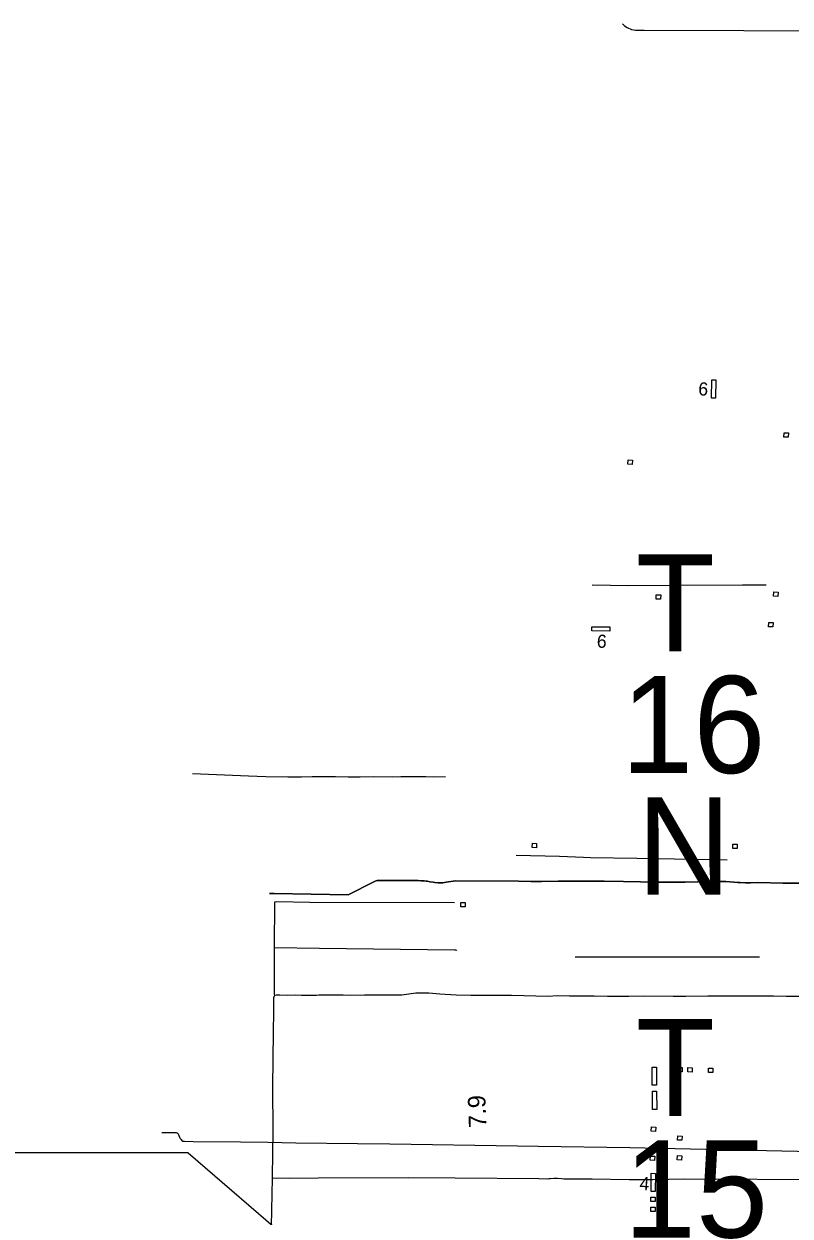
# Model space of a CAD drawing. Extents: x 1366406 to 1373462, y 376856 to 381998.
# Drawn here: x 1368782.4 to 1368990.1, y 380042.3 to 380365.3 of the extents above; entities that cross this region are included whole.
import ezdxf

# ---------------------------------------------------------------- set-up
doc = ezdxf.new("R2010")
doc.units = 0
for name, color, linetype in [('29', 7, 'Continuous'), ('31', 7, 'Continuous'), ('32', 7, 'Continuous'), ('43', 7, 'Continuous'), ('48', 7, 'Continuous'), ('56', 7, 'Continuous'), ('Default', 7, 'Continuous'), ('R_Draft', 7, 'Continuous')]:
    doc.layers.add(name, color=color, linetype=linetype)

msp = doc.modelspace()

# ---------------------------------------------------------------- linework, layer by layer
at = {"layer": '29'}
msp.add_lwpolyline([(1368992.81, 380132.52), (1368988.13, 380132.5), (1368981.33, 380132.65), (1368979.38, 380132.62), (1368977.99, 380132.61), (1368976.61, 380132.64), (1368975.96, 380132.7), (1368972.68, 380132.93), (1368971.68, 380132.97), (1368970.61, 380132.95), (1368965.11, 380132.81), (1368961.7, 380132.75), (1368959.74, 380132.73), (1368957.31, 380132.73), (1368953.06, 380132.77), (1368949.56, 380132.84), (1368944.99, 380132.9), (1368939.76, 380133.03), (1368937.33, 380133.06), (1368930.3, 380132.99), (1368927.21, 380132.99), (1368922.77, 380132.96), (1368919.85, 380132.96), (1368916.46, 380133.03), (1368899.4, 380133.12), (1368898.76, 380133.07), (1368898.15, 380132.98), (1368896.87, 380132.72), (1368895.99, 380132.6), (1368895.36, 380132.56), (1368894.72, 380132.57), (1368893.82, 380132.65), (1368893.4, 380132.73), (1368892.45, 380132.89), (1368891.81, 380133.02), (1368891.5, 380133.07), (1368890.92, 380133.11), (1368890.07, 380133.16), (1368889.33, 380133.19), (1368881.54, 380133.19), (1368878.51, 380133.2), (1368878.21, 380133.17), (1368877.91, 380133.11), (1368877.63, 380133.02), (1368877.26, 380132.83), (1368870.36, 380129.37), (1368850.31, 380129.67), (1368849.05, 380129.72)], dxfattribs=at)
at = {"layer": '31'}
for points in [[(1368828.11, 380162.23), (1368843.33, 380161.61)], [(1368843.33, 380161.61), (1368848.04, 380161.4), (1368854, 380161.34), (1368857.64, 380161.29), (1368860.56, 380161.39), (1368861.42, 380161.37), (1368865.33, 380161.37), (1368866.88, 380161.35), (1368870.3, 380161.33), (1368873.57, 380161.33), (1368877.33, 380161.37), (1368882.4, 380161.34), (1368884.59, 380161.37), (1368888.09, 380161.36), (1368891.37, 380161.36), (1368893.52, 380161.33), (1368896.73, 380161.36)]]:
    msp.add_lwpolyline(points, dxfattribs=at)
at = {"layer": '32'}
for points in [[(1368944.66, 380365.32), (1368945.27, 380364.79), (1368945.98, 380364.3), (1368947.17, 380363.76), (1368948.17, 380363.56), (1368949.47, 380363.57), (1368950.6, 380363.56), (1368977.56, 380363.5), (1368994.49, 380363.45), (1369014.52, 380363.36), (1369057.49, 380363.5), (1369079.6, 380363.29), (1369099.69, 380363.13), (1369120.87, 380363.07), (1369134.89, 380362.95), (1369142.96, 380362.92), (1369155.95, 380362.94), (1369165.49, 380362.98), (1369174.24, 380363.07), (1369180.67, 380363.1), (1369185.83, 380363.06)], [(1368936.46, 380213.32), (1368946.38, 380213.16), (1368959.2, 380213.22), (1368977.25, 380213.33), (1368983.67, 380213.35)], [(1368915.88, 380140.09), (1368927.63, 380139.77), (1368934.13, 380139.53), (1368936, 380139.49), (1368948.55, 380139.26), (1368958.81, 380139.1), (1368973.07, 380138.78)], [(1368849.05, 380129.72), (1368850.31, 380129.67), (1368870.36, 380129.37), (1368877.26, 380132.83), (1368877.63, 380133.02), (1368877.91, 380133.11), (1368878.21, 380133.17), (1368878.51, 380133.2), (1368881.54, 380133.19), (1368889.33, 380133.19), (1368890.07, 380133.16), (1368890.92, 380133.11), (1368891.5, 380133.07), (1368891.81, 380133.02), (1368892.45, 380132.89), (1368893.4, 380132.73), (1368893.82, 380132.65), (1368894.72, 380132.57), (1368895.36, 380132.56), (1368895.99, 380132.6), (1368896.87, 380132.72), (1368898.15, 380132.98), (1368898.76, 380133.07), (1368899.4, 380133.12), (1368916.46, 380133.03), (1368919.85, 380132.96), (1368922.77, 380132.96), (1368927.21, 380132.99), (1368930.3, 380132.99), (1368937.33, 380133.06), (1368939.76, 380133.03), (1368944.99, 380132.9), (1368949.56, 380132.84), (1368953.06, 380132.77), (1368957.31, 380132.73), (1368959.74, 380132.73), (1368961.7, 380132.75), (1368965.11, 380132.81), (1368970.61, 380132.95), (1368971.68, 380132.97), (1368972.68, 380132.93), (1368975.96, 380132.7), (1368976.61, 380132.64), (1368977.99, 380132.61), (1368979.38, 380132.62), (1368981.33, 380132.65), (1368988.13, 380132.5), (1368992.81, 380132.52)], [(1368850.35, 380115.05), (1368862.53, 380114.84), (1368899.15, 380114.45), (1368899.42, 380114.43), (1368899.68, 380114.35), (1368899.83, 380114.27)], [(1368819.79, 380064.98), (1368821.62, 380064.94), (1368822.5, 380064.94), (1368823.24, 380064.93), (1368823.52, 380064.93), (1368823.75, 380064.91), (1368823.91, 380064.88), (1368824.05, 380064.78), (1368824.25, 380064.57), (1368824.63, 380063.63), (1368824.82, 380063.27), (1368825.02, 380063), (1368825.24, 380062.79), (1368825.54, 380062.62), (1368825.94, 380062.56), (1368828.35, 380062.5), (1368841.17, 380062.37), (1368848.52, 380062.28), (1368856.17, 380062.18), (1368872.87, 380061.97), (1368881.66, 380061.87), (1368916.2, 380061.37), (1368921.8, 380061.26), (1368946.71, 380060.85), (1368959.01, 380060.58), (1368983.73, 380060.04), (1368996.24, 380059.79)]]:
    msp.add_lwpolyline(points, dxfattribs=at)
at = {"layer": '43'}
for points in [[(1368899.13, 380127.15), (1368859.97, 380127.22), (1368850.97, 380127.41), (1368850.34, 380127.36), (1368850.26, 380115.08), (1368850.28, 380103.43), (1368850.24, 380102.97), (1368850.3, 380102.55), (1368850.4, 380102.06), (1368850.13, 380101.43), (1368850.05, 380101.1), (1368850.09, 380097.67), (1368850.01, 380092.18), (1368849.83, 380077.32), (1368849.88, 380065.33), (1368849.69, 380053.06), (1368849.71, 380052.56), (1368849.45, 380039.54)], [(1368998.61, 380101.76), (1368989.09, 380101.8), (1368985.59, 380101.86), (1368981.24, 380101.9), (1368967.84, 380101.9), (1368961.82, 380101.81), (1368958.39, 380101.82), (1368950.61, 380101.84), (1368946.44, 380101.78), (1368940.64, 380101.81), (1368936.97, 380101.89), (1368933.98, 380101.9), (1368930.34, 380101.89), (1368926.98, 380101.97), (1368924.57, 380101.83), (1368914.62, 380102.02), (1368903.55, 380102.1), (1368899.64, 380102.16), (1368895.14, 380102.46), (1368892.17, 380102.67), (1368888.65, 380102.67), (1368884.88, 380102.12), (1368879.23, 380102.18), (1368874.79, 380102.15), (1368871.05, 380102.1), (1368869.02, 380102.13), (1368867.6, 380102.13), (1368864.53, 380102.15), (1368862.38, 380102.12), (1368861.76, 380102.09), (1368860.46, 380102.06), (1368857.64, 380102.08), (1368856.01, 380102.13), (1368853.79, 380102.06), (1368851.77, 380102.18), (1368850.77, 380102.12), (1368850.4, 380102.06)], [(1369000.85, 380052.15), (1368961.62, 380052.27), (1368952.87, 380052.15), (1368948.76, 380052.1), (1368946.5, 380052.15), (1368936.5, 380052.27), (1368929.62, 380052.29), (1368928.75, 380052.32), (1368928.14, 380052.38), (1368927.1, 380052.45), (1368926.68, 380052.46), (1368926.12, 380052.44), (1368925.19, 380052.41), (1368924.76, 380052.34), (1368924.27, 380052.25), (1368921.98, 380052.37), (1368899.33, 380052.59), (1368886.79, 380052.67), (1368862.23, 380052.56), (1368854.48, 380052.5), (1368849.71, 380052.56)]]:
    msp.add_lwpolyline(points, dxfattribs=at)
at = {"layer": '56'}
for points in [[(1368968.89, 380268.84), (1368970.02, 380268.83), (1368969.94, 380263.91), (1368968.82, 380263.92)], [(1368988.4, 380253.36), (1368988.47, 380254.53), (1368989.64, 380254.46), (1368989.57, 380253.29)], [(1368946.18, 380246.03), (1368946.25, 380247.2), (1368947.43, 380247.13), (1368947.35, 380245.96)], [(1368953.84, 380209.47), (1368953.86, 380210.64), (1368955.04, 380210.62), (1368955.02, 380209.45)], [(1368985.63, 380210.24), (1368985.71, 380211.41), (1368986.88, 380211.33), (1368986.8, 380210.17)], [(1368936.36, 380200.82), (1368936.37, 380201.94), (1368941.29, 380201.9), (1368941.29, 380200.78)], [(1368984.27, 380201.98), (1368984.34, 380203.15), (1368985.52, 380203.08), (1368985.44, 380201.91)], [(1368920.18, 380142.13), (1368920.25, 380143.3), (1368921.42, 380143.23), (1368921.35, 380142.06)], [(1368960.86, 380142.22), (1368960.87, 380143.39), (1368962.05, 380143.39), (1368962.04, 380142.22)], [(1368974.56, 380141.87), (1368974.57, 380143.05), (1368975.74, 380143.04), (1368975.74, 380141.87)], [(1368900.84, 380126.04), (1368900.84, 380127.21), (1368902.02, 380127.21), (1368902.02, 380126.04)], [(1368952.74, 380082.64), (1368953.87, 380082.65), (1368953.9, 380077.73), (1368952.77, 380077.72)], [(1368959.71, 380081.38), (1368959.7, 380082.56), (1368960.88, 380082.56), (1368960.88, 380081.39)], [(1368962.36, 380081.35), (1368962.43, 380082.52), (1368963.6, 380082.45), (1368963.53, 380081.28)], [(1368968.02, 380081.19), (1368968.04, 380082.36), (1368969.21, 380082.34), (1368969.19, 380081.17)], [(1368952.81, 380076.1), (1368953.93, 380076.1), (1368953.97, 380071.18), (1368952.84, 380071.17)], [(1368952.44, 380065.28), (1368952.51, 380066.45), (1368953.68, 380066.38), (1368953.61, 380065.21)], [(1368959.59, 380062.9), (1368959.67, 380064.07), (1368960.84, 380063.99), (1368960.77, 380062.82)], [(1368952.24, 380059.91), (1368952.31, 380061.08), (1368953.49, 380061), (1368953.41, 380059.83)], [(1368959.51, 380057.56), (1368959.58, 380058.73), (1368960.76, 380058.65), (1368960.68, 380057.48)], [(1368952.22, 380057.4), (1368952.29, 380058.57), (1368953.46, 380058.5), (1368953.39, 380057.33)], [(1368952.49, 380053.88), (1368953.62, 380053.86), (1368953.55, 380048.94), (1368952.42, 380048.95)], [(1368952.39, 380046.25), (1368952.38, 380047.42), (1368953.56, 380047.42), (1368953.56, 380046.25)], [(1368952.37, 380043.53), (1368952.38, 380044.7), (1368953.55, 380044.7), (1368953.55, 380043.53)]]:
    msp.add_lwpolyline(points, close=True, dxfattribs=at)
at = {"layer": 'Default'}
for p, q in [((1368931.84, 380112.56), (1368981.84, 380112.56)), ((1368826.95, 380059.41), (1369196.47, 379741.86))]:
    msp.add_line(p, q, dxfattribs=at)
at = {"layer": 'R_Draft'}
msp.add_line((1368826.95, 380059.41), (1368409.33, 380059.41), dxfattribs=at)

# ---------------------------------------------------------------- texts
at = {"layer": '48'}
msp.add_text('7.9', height=4.752, rotation=92.3907, dxfattribs=at).set_placement((1368907.83, 380066.33))
at = {"layer": '56'}
for s, p in [('6', (1368965.15, 380264.7)), ('6', (1368937.65, 380196.35)), ('4', (1368949.22, 380049.41))]:
    msp.add_text(s, height=3.56, rotation=356.4139, dxfattribs=at).set_placement(p)
at = {"layer": 'Default'}
for s, p in [('T', (1368948.25, 380195.26)), ('16', (1368944.31, 380162.34)), ('N', (1368948.66, 380129.41)), ('T', (1368948.25, 380069.41)), ('15', (1368945.04, 380036.48))]:
    msp.add_text(s, height=26.3, dxfattribs=at).set_placement(p)

doc.saveas('drawing.dxf')
